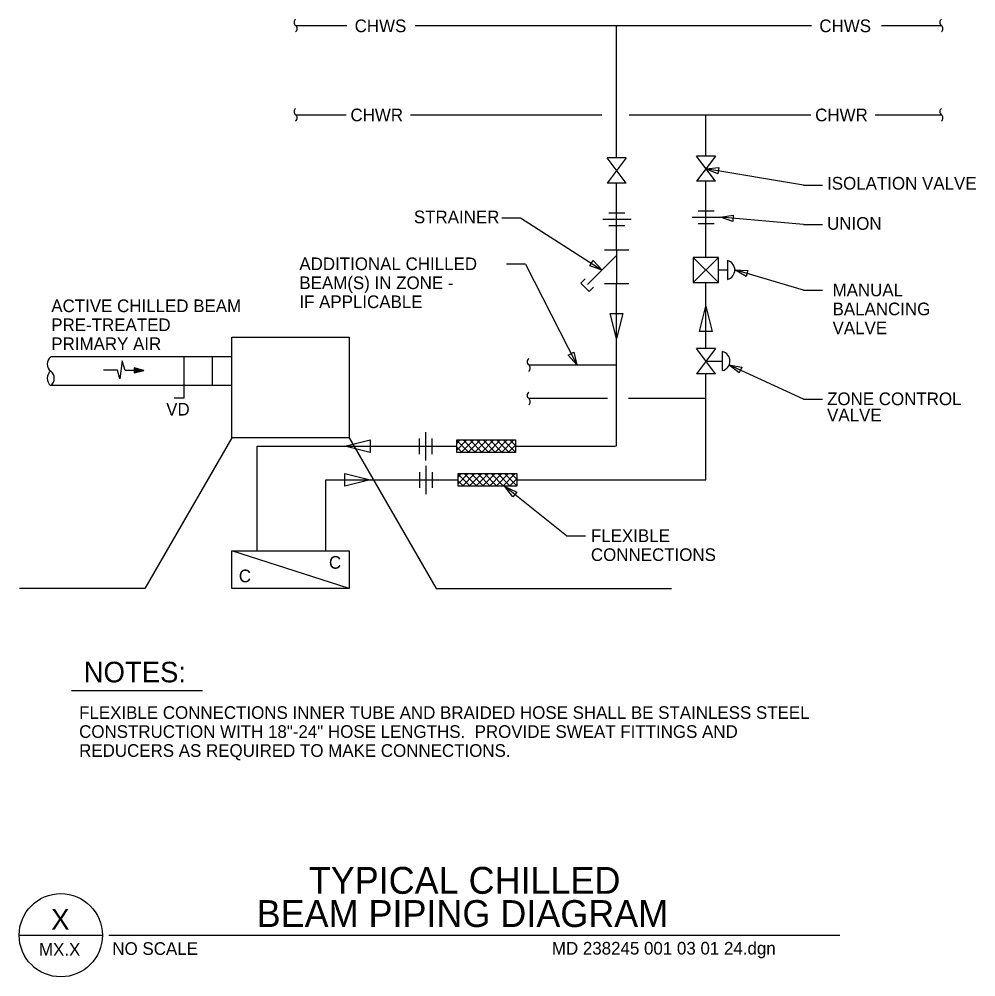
# Model space of a CAD drawing. Extents: x 10621.1 to 10671.6, y 10042.5 to 10093.
import ezdxf

# ---------------------------------------------------------------- set-up
doc = ezdxf.new("R2010")
doc.units = 0
for name, color, linetype in [('G-ANNO-CELL', 7, 'Continuous'), ('G-ANNO-TEXT', 7, 'Continuous'), ('G-DETL-TEXT', 7, 'Continuous')]:
    doc.layers.add(name, color=color, linetype=linetype)

msp = doc.modelspace()

# ---------------------------------------------------------------- linework, layer by layer
at = {"layer": 'G-ANNO-CELL'}
for p, q in [((10623.893, 10057.583), (10630.797, 10057.583)), ((10621.143, 10044.69), (10625.528, 10044.69)), ((10625.874, 10044.69), (10664.399, 10044.69))]:
    msp.add_line(p, q, dxfattribs=at)
msp.add_circle((10623.336, 10044.69), 2.193, dxfattribs=at)
at = {"layer": 'G-ANNO-TEXT'}
for p, q in [((10662.471, 10084.214), (10657.337, 10085.081)), ((10662.471, 10084.214), (10663.471, 10084.214)), ((10646.571, 10082.494), (10647.571, 10082.494)), ((10647.571, 10082.494), (10651.866, 10079.738)), ((10662.471, 10082.144), (10658.098, 10082.522)), ((10662.471, 10082.144), (10663.471, 10082.144)), ((10647.825, 10080.045), (10646.825, 10080.045)), ((10647.825, 10080.045), (10650.527, 10074.739)), ((10662.471, 10078.672), (10658.86, 10079.742)), ((10662.471, 10078.672), (10663.471, 10078.672)), ((10662.471, 10072.939), (10658.545, 10074.747)), ((10662.471, 10072.939), (10663.471, 10072.939)), ((10649.985, 10065.733), (10646.742, 10068.328)), ((10649.985, 10065.733), (10650.985, 10065.733))]:
    msp.add_line(p, q, dxfattribs=at)
for points in [[(10657.967, 10084.806), (10657.337, 10085.081), (10658.022, 10085.135)], [(10658.747, 10082.298), (10658.098, 10082.522), (10658.776, 10082.63)], [(10651.395, 10080.238), (10651.866, 10079.738), (10651.215, 10079.957)], [(10659.451, 10079.393), (10658.86, 10079.742), (10659.546, 10079.713)], [(10656.998, 10076.504), (10657.331, 10077.837), (10657.664, 10076.504)], [(10652.963, 10077.458), (10652.629, 10076.125), (10652.296, 10077.458)], [(10650.373, 10075.409), (10650.527, 10074.739), (10650.076, 10075.258)], [(10659.081, 10074.317), (10658.545, 10074.747), (10659.22, 10074.62)], [(10639.64, 10070.121), (10638.307, 10070.455), (10639.64, 10070.788)], [(10638.309, 10069.016), (10639.642, 10068.683), (10638.309, 10068.35)], [(10647.158, 10067.782), (10646.742, 10068.328), (10647.366, 10068.042)]]:
    msp.add_lwpolyline(points, close=True, dxfattribs=at)
at = {"layer": 'G-DETL-TEXT'}
for p, q in [((10635.712, 10092.626), (10638.414, 10092.626)), ((10642.017, 10092.626), (10662.902, 10092.626)), ((10652.629, 10085.653), (10652.629, 10092.626)), ((10666.59, 10092.626), (10669.745, 10092.626)), ((10635.712, 10087.924), (10638.371, 10087.924)), ((10641.77, 10087.924), (10651.856, 10087.924)), ((10653.292, 10087.924), (10657.331, 10087.924)), ((10657.331, 10085.748), (10657.331, 10087.924)), ((10657.331, 10087.924), (10662.859, 10087.924)), ((10666.259, 10087.924), (10669.745, 10087.924)), ((10653.129, 10085.653), (10652.129, 10085.653)), ((10653.129, 10085.653), (10652.129, 10084.32)), ((10653.129, 10084.32), (10652.129, 10085.653)), ((10657.837, 10085.748), (10656.837, 10085.748)), ((10657.837, 10085.748), (10656.837, 10084.415)), ((10657.837, 10084.415), (10656.837, 10085.748)), ((10653.129, 10084.32), (10652.129, 10084.32)), ((10652.629, 10080.788), (10652.629, 10084.32)), ((10657.837, 10084.415), (10656.837, 10084.415)), ((10657.331, 10080.404), (10657.331, 10084.415)), ((10652.219, 10082.76), (10653.053, 10082.76)), ((10656.927, 10082.855), (10657.761, 10082.855)), ((10651.896, 10082.427), (10653.39, 10082.427)), ((10656.604, 10082.522), (10658.098, 10082.522)), ((10652.219, 10082.094), (10653.053, 10082.094)), ((10656.927, 10082.188), (10657.761, 10082.188)), ((10653.271, 10080.788), (10651.987, 10080.788)), ((10652.629, 10080.788), (10652.629, 10079.018)), ((10652.629, 10080.501), (10651.102, 10078.975)), ((10657.993, 10080.404), (10656.67, 10079.081)), ((10657.993, 10079.081), (10656.67, 10080.404)), ((10658.473, 10080.242), (10658.473, 10079.242)), ((10657.993, 10079.742), (10658.473, 10079.742)), ((10650.743, 10079.056), (10650.97, 10079.283)), ((10650.743, 10079.056), (10651.182, 10078.617)), ((10651.182, 10078.617), (10651.409, 10078.844)), ((10653.271, 10079.018), (10651.987, 10079.018)), ((10652.629, 10070.455), (10652.629, 10079.018)), ((10657.331, 10075.608), (10657.331, 10079.081)), ((10657.831, 10075.608), (10656.831, 10075.608)), ((10657.831, 10074.274), (10656.831, 10075.608)), ((10657.831, 10075.608), (10656.831, 10074.274)), ((10658.214, 10074.441), (10658.214, 10075.441)), ((10631.307, 10075.159), (10622.808, 10075.159)), ((10626.579, 10074.963), (10626.456, 10074.016)), ((10626.727, 10074.453), (10626.579, 10074.963)), ((10629.819, 10075.159), (10629.819, 10072.983)), ((10632.347, 10075.159), (10631.307, 10075.159)), ((10631.307, 10075.159), (10631.307, 10073.659)), ((10652.629, 10074.736), (10647.995, 10074.736)), ((10657.331, 10074.941), (10658.214, 10074.941)), ((10626.333, 10074.463), (10625.596, 10074.463)), ((10626.456, 10074.016), (10626.333, 10074.463)), ((10627.707, 10074.45), (10626.727, 10074.45)), ((10627.212, 10074.58), (10627.212, 10074.327)), ((10627.719, 10074.453), (10627.212, 10074.58)), ((10627.212, 10074.58), (10627.212, 10074.327)), ((10627.212, 10074.547), (10627.389, 10074.371)), ((10627.212, 10074.508), (10627.357, 10074.363)), ((10627.212, 10074.468), (10627.325, 10074.355)), ((10627.212, 10074.327), (10627.719, 10074.453)), ((10627.212, 10074.428), (10627.294, 10074.347)), ((10627.212, 10074.388), (10627.262, 10074.339)), ((10627.212, 10074.349), (10627.23, 10074.331)), ((10627.222, 10074.577), (10627.421, 10074.379)), ((10627.275, 10074.564), (10627.453, 10074.387)), ((10627.328, 10074.551), (10627.485, 10074.395)), ((10627.381, 10074.537), (10627.516, 10074.403)), ((10627.434, 10074.524), (10627.548, 10074.411)), ((10627.488, 10074.511), (10627.58, 10074.418)), ((10627.541, 10074.498), (10627.612, 10074.426)), ((10627.594, 10074.484), (10627.644, 10074.434)), ((10627.647, 10074.471), (10627.675, 10074.442)), ((10627.7, 10074.458), (10627.707, 10074.45)), ((10657.831, 10074.274), (10656.831, 10074.274)), ((10657.331, 10068.683), (10657.331, 10074.274)), ((10631.307, 10073.659), (10622.808, 10073.659)), ((10632.347, 10073.659), (10631.307, 10073.659)), ((10629.819, 10072.983), (10629.319, 10072.983)), ((10652.144, 10072.964), (10647.995, 10072.964)), ((10657.331, 10072.964), (10653.261, 10072.964)), ((10642.581, 10069.708), (10642.581, 10071.202)), ((10632.347, 10070.902), (10627.758, 10062.953)), ((10638.526, 10070.902), (10643.115, 10062.953)), ((10642.248, 10070.031), (10642.248, 10070.865)), ((10642.915, 10070.031), (10642.915, 10070.865)), ((10644.209, 10070.605), (10644.39, 10070.786)), ((10644.209, 10070.251), (10644.743, 10070.786)), ((10644.209, 10070.757), (10644.837, 10070.128)), ((10644.439, 10070.128), (10645.097, 10070.786)), ((10644.534, 10070.786), (10645.191, 10070.128)), ((10644.793, 10070.128), (10645.45, 10070.786)), ((10644.887, 10070.786), (10645.544, 10070.128)), ((10645.146, 10070.128), (10645.804, 10070.786)), ((10645.241, 10070.786), (10645.898, 10070.128)), ((10645.5, 10070.128), (10646.157, 10070.786)), ((10645.594, 10070.786), (10646.252, 10070.128)), ((10645.854, 10070.128), (10646.511, 10070.786)), ((10645.948, 10070.786), (10646.605, 10070.128)), ((10646.207, 10070.128), (10646.864, 10070.786)), ((10646.301, 10070.786), (10646.959, 10070.128)), ((10646.561, 10070.128), (10647.218, 10070.786)), ((10646.655, 10070.786), (10647.298, 10070.142)), ((10647.008, 10070.786), (10647.298, 10070.496)), ((10633.687, 10070.455), (10644.209, 10070.455)), ((10633.687, 10064.944), (10633.687, 10070.455)), ((10644.209, 10070.403), (10644.484, 10070.128)), ((10646.914, 10070.128), (10647.298, 10070.512)), ((10647.268, 10070.128), (10647.298, 10070.159)), ((10647.298, 10070.455), (10652.561, 10070.455)), ((10642.599, 10067.936), (10642.599, 10069.43)), ((10637.298, 10068.683), (10644.277, 10068.683)), ((10637.298, 10064.944), (10637.298, 10068.683)), ((10642.266, 10068.259), (10642.266, 10069.093)), ((10642.933, 10068.259), (10642.933, 10069.093)), ((10644.277, 10068.833), (10644.458, 10069.014)), ((10644.277, 10068.479), (10644.811, 10069.014)), ((10644.277, 10068.985), (10644.905, 10068.356)), ((10644.277, 10068.631), (10644.552, 10068.356)), ((10644.507, 10068.356), (10645.165, 10069.014)), ((10644.602, 10069.014), (10645.259, 10068.356)), ((10644.861, 10068.356), (10645.518, 10069.014)), ((10644.955, 10069.014), (10645.612, 10068.356)), ((10645.214, 10068.356), (10645.872, 10069.014)), ((10645.309, 10069.014), (10645.966, 10068.356)), ((10645.568, 10068.356), (10646.225, 10069.014)), ((10645.662, 10069.014), (10646.32, 10068.356)), ((10645.921, 10068.356), (10646.579, 10069.014)), ((10646.016, 10069.014), (10646.673, 10068.356)), ((10646.275, 10068.356), (10646.932, 10069.014)), ((10646.369, 10069.014), (10647.027, 10068.356)), ((10646.629, 10068.356), (10647.286, 10069.014)), ((10646.723, 10069.014), (10647.366, 10068.37)), ((10646.982, 10068.356), (10647.366, 10068.74)), ((10647.076, 10069.014), (10647.366, 10068.724)), ((10647.366, 10068.683), (10657.331, 10068.683)), ((10647.336, 10068.356), (10647.366, 10068.387)), ((10638.526, 10062.953), (10632.347, 10064.944)), ((10627.758, 10062.953), (10621.169, 10062.953)), ((10643.115, 10062.953), (10655.524, 10062.953))]:
    msp.add_line(p, q, dxfattribs=at)
for points in [[(10656.67, 10080.404), (10656.67, 10079.081), (10657.993, 10079.081), (10657.993, 10080.404)], [(10632.347, 10076.211), (10638.526, 10076.211), (10638.526, 10070.902), (10632.347, 10070.902)], [(10644.209, 10070.787), (10647.298, 10070.787), (10647.298, 10070.123), (10644.209, 10070.123)], [(10644.277, 10069.015), (10647.366, 10069.015), (10647.366, 10068.351), (10644.277, 10068.351)], [(10632.347, 10064.944), (10638.526, 10064.944), (10638.526, 10062.953), (10632.347, 10062.953)]]:
    msp.add_lwpolyline(points, close=True, dxfattribs=at)
for centre, radius, start, end in [((10635.837, 10092.793), 0.208, 126.8699, 233.1301), ((10669.87, 10092.793), 0.208, 126.8699, 233.1301), ((10635.587, 10092.459), 0.208, 306.8699, 53.1301), ((10669.62, 10092.459), 0.208, 306.8699, 53.1301), ((10635.837, 10088.091), 0.208, 126.8699, 233.1301), ((10635.587, 10087.757), 0.208, 306.8699, 53.1301), ((10669.87, 10088.091), 0.208, 126.8699, 233.1301), ((10669.62, 10087.757), 0.208, 306.8699, 53.1301), ((10658.343, 10079.742), 0.516, 284.5203, 75.4797), ((10658.084, 10074.941), 0.516, 284.5203, 75.4797), ((10623.089, 10074.784), 0.469, 126.8699, 233.1301), ((10648.12, 10074.903), 0.208, 126.8699, 233.1301), ((10647.87, 10074.57), 0.208, 306.8699, 53.1301), ((10623.089, 10074.034), 0.469, 126.8699, 233.1301), ((10622.526, 10074.034), 0.469, 306.8699, 53.1301), ((10648.12, 10073.131), 0.208, 126.8699, 233.1301), ((10647.87, 10072.798), 0.208, 306.8699, 53.1301)]:
    msp.add_arc(centre, radius, start, end, dxfattribs=at)

# ---------------------------------------------------------------- texts
at = {"layer": 'G-ANNO-CELL'}
for s, height, p in [('NOTES:', 1.0833, (10624.543, 10058.015)), ('TYPICAL CHILLED', 1.41667, (10636.406, 10046.873)), ('BEAM PIPING DIAGRAM', 1.41667, (10633.66, 10045.123)), ('X', 1.083, (10622.831, 10044.982)), ('MX.X', 0.6667, (10622.188, 10043.607)), ('NO SCALE', 0.6667, (10626.055, 10043.655))]:
    msp.add_text(s, height=height, dxfattribs=at).set_placement(p)
at = {"layer": 'G-ANNO-TEXT'}
for s, height, p in [('CHWS', 0.6667, (10638.823, 10092.274)), ('CHWS', 0.6667, (10663.312, 10092.274)), ('CHWR', 0.6667, (10638.602, 10087.578)), ('CHWR', 0.6667, (10663.091, 10087.578)), ('ISOLATION VALVE', 0.66667, (10663.72, 10083.979)), ('STRAINER', 0.6667, (10641.945, 10082.204)), ('UNION', 0.6667, (10663.72, 10081.861)), ('ADDITIONAL CHILLED', 0.66667, (10635.91, 10079.735)), ('BEAM(S) IN ZONE -', 0.66667, (10635.91, 10078.735)), ('MANUAL', 0.6667, (10664.008, 10078.358)), ('IF APPLICABLE', 0.66667, (10635.91, 10077.735)), ('ACTIVE CHILLED BEAM', 0.66667, (10622.836, 10077.522)), ('BALANCING', 0.6667, (10664.008, 10077.358)), ('PRE-TREATED', 0.66667, (10622.836, 10076.522)), ('VALVE', 0.6667, (10664.008, 10076.358)), ('PRIMARY AIR', 0.66667, (10622.836, 10075.522)), ('ZONE CONTROL', 0.66667, (10663.72, 10072.621)), ('VD', 0.6667, (10628.891, 10072.075)), ('VALVE', 0.6667, (10663.72, 10071.765)), ('FLEXIBLE', 0.6667, (10651.274, 10065.41)), ('C', 0.667, (10637.469, 10064.001)), ('CONNECTIONS', 0.66667, (10651.274, 10064.41)), ('C', 0.667, (10632.718, 10063.288)), ('FLEXIBLE CONNECTIONS INNER TUBE AND BRAIDED HOSE SHALL BE STAINLESS STEEL', 0.66667, (10624.303, 10056.089)), ('CONSTRUCTION WITH 18"-24" HOSE LENGTHS.  PROVIDE SWEAT FITTINGS AND', 0.66667, (10624.303, 10055.089)), ('REDUCERS AS REQUIRED TO MAKE CONNECTIONS.', 0.66667, (10624.303, 10054.089))]:
    msp.add_text(s, height=height, dxfattribs=at).set_placement(p)
at = {"layer": 'G-DETL-TEXT'}
msp.add_text('MD 238245 001 03 01 24.dgn', height=0.66667, dxfattribs=at).set_placement((10649.216, 10043.672))

doc.saveas('drawing.dxf')
